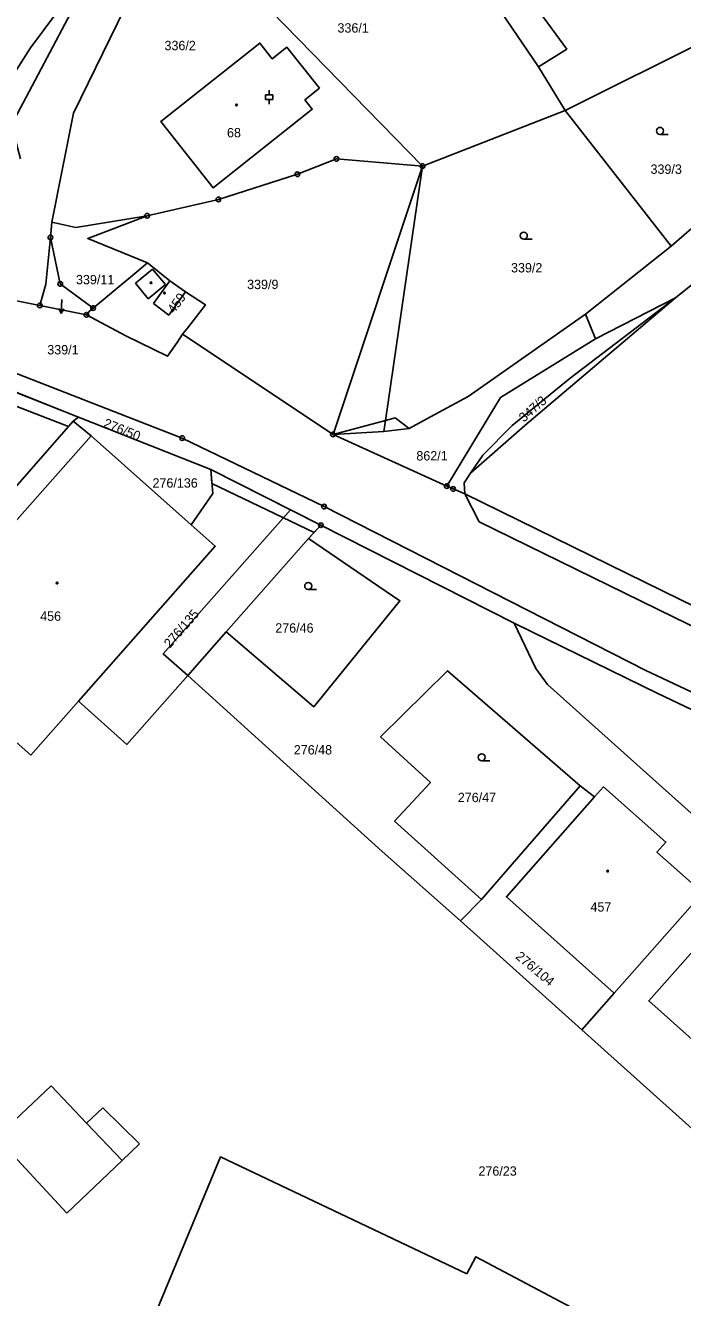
# Model space of a CAD drawing. Extents: x -745926 to -742978, y -968282 to -965689.
# Drawn here: x -745043.2 to -744972.9, y -966916.9 to -966781 of the extents above; entities that cross this region are included whole.
import ezdxf

# ---------------------------------------------------------------- set-up
doc = ezdxf.new("R2010")
doc.units = 0
for name, color, linetype in [('Hranice parcel', 7, 'Continuous'), ('Parcelní čísla', 7, 'Continuous'), ('Pop  PČ popisy', 7, 'Continuous'), ('Vnitřní kresba', 7, 'Continuous'), ('Věcná břemena k části', 7, 'Continuous'), ('Značky bodu BP', 7, 'Continuous'), ('Značky budov', 7, 'Continuous'), ('Značky kultur', 7, 'Continuous')]:
    doc.layers.add(name, color=color, linetype=linetype)

msp = doc.modelspace()

# ---------------------------------------------------------------- linework, layer by layer
at = {"layer": 'Hranice parcel'}
for p, q in [((-744988.3, -966785.4), (-745008.46, -966755.75)), ((-745025.37, -966770.73), (-745000.7, -966796)), ((-744963.69, -966779.18), (-744985.45, -966790.05)), ((-744985.45, -966790.05), (-744988.3, -966785.4)), ((-745000.7, -966796), (-744985.45, -966790.05)), ((-744974.13, -966804.56), (-744985.45, -966790.05)), ((-745040.49, -966803.62), (-745040.33, -966801.98)), ((-744983.3, -966811.81), (-744974.13, -966804.56)), ((-745041.62, -966810.89), (-745048.59, -966809.48)), ((-744973.68, -966810.09), (-744982.22, -966814.46)), ((-745036.63, -966811.89), (-745041.62, -966810.89)), ((-744982.22, -966814.46), (-744983.3, -966811.81)), ((-745010.28, -966824.67), (-745026.38, -966813.97)), ((-744982.22, -966814.46), (-744992.38, -966820.73)), ((-745047.24, -966818.95), (-745037.49, -966822.82)), ((-744992.38, -966820.73), (-744998.12, -966830.19)), ((-745037.49, -966822.82), (-745038.07, -966823.26)), ((-745037.49, -966822.82), (-745023.34, -966828.43)), ((-745010.28, -966824.67), (-745004.83, -966824.34)), ((-744998.12, -966830.19), (-745010.28, -966824.67)), ((-745023.34, -966828.43), (-745011.58, -966834.36)), ((-745011.58, -966834.36), (-745012.89, -966835.79)), ((-744990.92, -966844.83), (-745011.58, -966834.36)), ((-745012.89, -966835.79), (-745021.7, -966845.74)), ((-744988.59, -966849.68), (-744990.92, -966844.83)), ((-745021.7, -966845.74), (-745025.78, -966850.42)), ((-744994.4, -966874.34), (-744983.86, -966862.22)), ((-744983.86, -966862.22), (-744982.34, -966863.4)), ((-744996.64, -966876.63), (-744994.4, -966874.34)), ((-744983.68, -966888.27), (-744996.64, -966876.63)), ((-744980.22, -966884.36), (-744983.68, -966888.27)), ((-744961.49, -966908.2), (-744983.68, -966888.27))]:
    msp.add_line(p, q, dxfattribs=at)
for points in [[(-744988.3, -966785.4), (-744985.3, -966783.5), (-744994.24, -966771.28), (-745006.6, -966754.49)], [(-745025.37, -966770.73), (-745032.52, -966779.12), (-745038.02, -966790.33), (-745040.33, -966801.98)], [(-745043.69, -966795.22), (-745044.66, -966791.59), (-745034.52, -966772.46)], [(-745011.73, -966787.69), (-745015.21, -966783.3), (-745016.77, -966784.55), (-745018.1, -966782.86), (-745028.69, -966791.24), (-745023.09, -966798.31), (-745012.5, -966789.93), (-745013.29, -966788.93), (-745011.73, -966787.69)], [(-744974.13, -966804.56), (-744970.61, -966801.49), (-744955.56, -966790.15), (-744951.43, -966784.53)], [(-744953.64, -966793.11), (-744957.67, -966797.25), (-744973.68, -966810.09)], [(-745030.15, -966801.31), (-745022.53, -966799.56), (-745014.09, -966796.87), (-745009.91, -966795.24), (-745000.7, -966796)], [(-745000.7, -966796), (-745004.66, -966823.19), (-745004.83, -966824.34)], [(-745040.33, -966801.98), (-745037.77, -966802.57), (-745030.15, -966801.31)], [(-745030.15, -966801.31), (-745036.49, -966803.73), (-745030.09, -966806.35)], [(-745040.49, -966803.62), (-745040.97, -966808.61), (-745041.62, -966810.89)], [(-745035.93, -966811.17), (-745039.44, -966808.59), (-745040.49, -966803.62)], [(-745030.09, -966806.35), (-745031.93, -966807.87), (-745032.91, -966808.69), (-745035.93, -966811.17)], [(-745026.38, -966813.97), (-745025.84, -966813.3), (-745023.92, -966810.81), (-745026.06, -966809.43), (-745027.71, -966808.27), (-745030.09, -966806.35)], [(-744973.68, -966810.09), (-744989.77, -966823.72), (-744995.58, -966828.81)], [(-745035.93, -966811.17), (-745036.35, -966811.52), (-745036.63, -966811.89)], [(-745036.63, -966811.89), (-745032.42, -966814.14), (-745027.96, -966816.31), (-745026.94, -966814.86), (-745026.38, -966813.97)], [(-745004.83, -966824.34), (-745002.13, -966824.04), (-744999.85, -966822.8), (-744995.82, -966820.61), (-744983.3, -966811.81)], [(-744976.86, -966849.87), (-745011.23, -966832.38), (-745026.4, -966825.06), (-745046.24, -966817.33), (-745048.48, -966816.48), (-745051.47, -966815.51)], [(-745038.07, -966823.26), (-745047.51, -966834), (-745045.67, -966835.62), (-745046.6, -966836.67)], [(-745025.45, -966834.32), (-745036.12, -966824.82), (-745038.07, -966823.26)], [(-745023.34, -966828.43), (-745023.14, -966830.97), (-745025.45, -966834.32)], [(-744995.58, -966828.81), (-744996.27, -966829.83), (-744996.19, -966831.03)], [(-744996.19, -966831.03), (-744997.45, -966830.49), (-744998.12, -966830.19)], [(-744952.72, -966850.89), (-744955.64, -966850.83), (-744973.11, -966842.35), (-744996.19, -966831.03)], [(-745037.48, -966853.16), (-745022.87, -966836.61), (-745025.45, -966834.32)], [(-745021.7, -966845.74), (-745012.34, -966853.76), (-745003.12, -966842.43), (-745012.89, -966835.79)], [(-745046.6, -966836.67), (-745055.88, -966847.18), (-745042.58, -966858.93), (-745037.48, -966853.16)], [(-744990.92, -966844.83), (-744975.55, -966852.34), (-744962.29, -966858.63), (-744955.54, -966861.5)], [(-745025.78, -966850.42), (-745032.31, -966857.79), (-745037.48, -966853.16)], [(-744996.64, -966876.63), (-745005.03, -966869.23), (-745025.78, -966850.42)], [(-744983.86, -966862.22), (-744998.05, -966849.92), (-745005.2, -966856.96), (-744999.86, -966861.87), (-745003.7, -966865.98), (-744994.4, -966874.34)], [(-744967.24, -966869.4), (-744987.36, -966851.37), (-744988.59, -966849.68)], [(-744931.91, -966869.84), (-744944.58, -966864.36), (-744947.95, -966862.9), (-744962.44, -966856.66), (-744976.86, -966849.87)], [(-744980.22, -966884.36), (-744970.75, -966873.64), (-744975.66, -966869.3), (-744974.7, -966868.21), (-744981.37, -966862.32), (-744982.34, -966863.4)], [(-744982.34, -966863.4), (-744991.74, -966874.07), (-744980.22, -966884.36)], [(-744967.04, -966874.5), (-744976.54, -966885.19), (-744958.34, -966901.38)], [(-744995.98, -966914.33), (-744995.01, -966912.52), (-744978.74, -966921.14), (-744935.57, -966945.39), (-744906.97, -966965.7), (-744924.97, -967001.59), (-744930.23, -967012.94), (-745036.56, -966960.9), (-745034.85, -966937.91), (-745034.73, -966931.79), (-745022.32, -966901.86), (-744995.98, -966914.33)]]:
    msp.add_lwpolyline(points, dxfattribs=at)
at = {"layer": 'Pop  PČ popisy'}
for p, q in [((-745039.33, -966811.74), (-745039.57, -966811.23)), ((-745039.28, -966810.24), (-745039.33, -966811.74)), ((-745039.33, -966811.74), (-745039.06, -966811.25))]:
    msp.add_line(p, q, dxfattribs=at)
at = {"layer": 'Vnitřní kresba'}
for p, q in [((-745042.62, -966783.36), (-745034.52, -966772.46)), ((-745044.62, -966786.49), (-745042.62, -966783.36)), ((-745000.7, -966796), (-745010.28, -966824.67)), ((-745031.4, -966808.52), (-745029.56, -966807)), ((-745029.56, -966807), (-745028.19, -966808.66)), ((-745030.03, -966810.18), (-745031.4, -966808.52)), ((-745028.19, -966808.66), (-745030.03, -966810.18)), ((-745027.71, -966808.27), (-745029.46, -966810.69)), ((-745027.81, -966811.92), (-745026.06, -966809.43)), ((-744973.68, -966810.09), (-744984.93, -966818.64)), ((-745029.46, -966810.69), (-745027.81, -966811.92)), ((-744991.14, -966823.71), (-744984.93, -966818.64)), ((-745010.28, -966824.67), (-745004.66, -966823.19)), ((-745003.63, -966822.91), (-745004.66, -966823.19)), ((-745002.13, -966824.04), (-745003.63, -966822.91)), ((-744991.14, -966823.71), (-744994.27, -966826.87)), ((-745045.67, -966835.62), (-745036.12, -966824.82)), ((-744994.27, -966826.87), (-744995.58, -966828.81)), ((-744996.19, -966831.03), (-744994.65, -966834)), ((-744994.65, -966834), (-744973.92, -966844.16)), ((-744956.53, -966852.61), (-744973.92, -966844.16)), ((-745046.24, -966899.76), (-745040.39, -966894.26)), ((-745040.39, -966894.26), (-745036.61, -966898.25)), ((-745036.61, -966898.25), (-745034.88, -966896.6)), ((-745034.88, -966896.6), (-745030.97, -966900.45)), ((-745036.61, -966898.25), (-745032.83, -966902.23)), ((-745038.74, -966907.86), (-745046.24, -966899.76)), ((-745030.97, -966900.45), (-745032.83, -966902.23)), ((-745032.83, -966902.23), (-745038.74, -966907.86))]:
    msp.add_line(p, q, dxfattribs=at)
at = {"layer": 'Věcná břemena k části'}
for points in [[(-745048.24, -966820.09), (-745038.56, -966823.82), (-745038.07, -966823.26), (-745037.49, -966822.82), (-745047.24, -966818.95), (-745047.37, -966819.16)], [(-745023.22, -966829.91), (-745012.3, -966835.14), (-745011.58, -966834.36), (-745014.83, -966832.72), (-745023.34, -966828.43)], [(-745025.78, -966850.42), (-745021.7, -966845.74), (-745012.89, -966835.79), (-745012.3, -966835.14), (-745011.58, -966834.36), (-745014.83, -966832.72), (-745028.42, -966848.12)]]:
    msp.add_lwpolyline(points, close=True, dxfattribs=at)
at = {"layer": 'Značky bodu BP'}
for centre, radius in [((-745009.91, -966795.24), 0.25), ((-745009.91, -966795.24), 0.0152), ((-745000.7, -966796), 0.25), ((-745000.7, -966796), 0.0152), ((-745014.09, -966796.87), 0.25), ((-745014.09, -966796.87), 0.0152), ((-745022.53, -966799.56), 0.25), ((-745022.53, -966799.56), 0.0152), ((-745030.15, -966801.31), 0.25), ((-745030.15, -966801.31), 0.0152), ((-745040.49, -966803.62), 0.25), ((-745040.49, -966803.62), 0.0152), ((-745039.44, -966808.59), 0.25), ((-745039.44, -966808.59), 0.0152), ((-745041.62, -966810.89), 0.25), ((-745041.62, -966810.89), 0.0152), ((-745035.93, -966811.17), 0.25), ((-745035.93, -966811.17), 0.0152), ((-745036.63, -966811.89), 0.25), ((-745036.63, -966811.89), 0.0152), ((-745026.4, -966825.06), 0.25), ((-745026.4, -966825.06), 0.0152), ((-745010.28, -966824.67), 0.25), ((-745010.28, -966824.67), 0.0152), ((-744998.12, -966830.19), 0.25), ((-744998.12, -966830.19), 0.0152), ((-744997.45, -966830.49), 0.25), ((-744997.45, -966830.49), 0.0152), ((-745011.23, -966832.38), 0.25), ((-745011.23, -966832.38), 0.0152), ((-745011.58, -966834.36), 0.25), ((-745011.58, -966834.36), 0.0152)]:
    msp.add_circle(centre, radius, dxfattribs=at)
at = {"layer": 'Značky budov'}
for centre in [(-745020.59, -966789.48), (-745029.74, -966808.47), (-745028.29, -966809.56), (-745039.77, -966840.55), (-744980.93, -966871.32)]:
    msp.add_circle(centre, 0.0875, dxfattribs=at)
at = {"layer": 'Značky kultur'}
for p, q in [((-745017.48, -966788.4), (-745016.72, -966788.4)), ((-745017.48, -966788.9), (-745017.48, -966788.4)), ((-745017.1, -966788.4), (-745017.1, -966787.9)), ((-745016.72, -966788.9), (-745016.72, -966788.4)), ((-745017.48, -966788.9), (-745016.72, -966788.9)), ((-745017.1, -966789.4), (-745017.1, -966788.9)), ((-744975.33, -966792.62), (-744974.45, -966792.62)), ((-744989.89, -966803.81), (-744989.01, -966803.81)), ((-745012.93, -966841.24), (-745012.05, -966841.24)), ((-744994.38, -966859.54), (-744993.5, -966859.54))]:
    msp.add_line(p, q, dxfattribs=at)
for centre in [(-744975.33, -966792.24), (-744989.89, -966803.43), (-745012.93, -966840.86), (-744994.38, -966859.16)]:
    msp.add_circle(centre, 0.375, dxfattribs=at)

# ---------------------------------------------------------------- texts
at = {"layer": 'Parcelní čísla'}
for s, p in [('336/1', (-745009.8, -966781.74)), ('336/2', (-745028.29, -966783.62)), ('68', (-745021.61, -966792.93)), ('339/3', (-744976.34, -966796.83)), ('339/2', (-744991.25, -966807.36)), ('339/11', (-745037.75, -966808.63)), ('339/9', (-745019.46, -966809.14)), ('339/1', (-745040.82, -966816.12)), ('862/1', (-745001.37, -966827.45)), ('276/136', (-745029.57, -966830.35)), ('456', (-745041.58, -966844.58)), ('276/46', (-745016.45, -966845.84)), ('276/48', (-745014.47, -966858.86)), ('276/47', (-744996.94, -966863.95)), ('457', (-744982.76, -966875.64)), ('276/23', (-744994.73, -966903.86))]:
    msp.add_text(s, height=1, dxfattribs=at).set_placement(p)
for s, rotation, p in [('459', 54, (-745027.26, -966811.83)), ('347/3', 41, (-744989.88, -966823.41)), ('276/50', 338, (-745034.9, -966823.84)), ('276/135', 49, (-745027.7, -966847.55)), ('276/104', 320, (-744990.85, -966880.57))]:
    msp.add_text(s, height=1, rotation=rotation, dxfattribs=at).set_placement(p)

doc.saveas('drawing.dxf')
